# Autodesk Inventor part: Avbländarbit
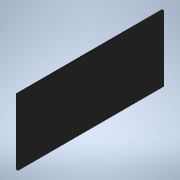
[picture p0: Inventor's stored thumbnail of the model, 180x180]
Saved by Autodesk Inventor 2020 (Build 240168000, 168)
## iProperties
Created: 2019-06
Part Number: Avbländarbit
Material: Acetal Resin, Black
Document SubType Name: Modeling
Designer: cl
Density: 1.425 g/cm^3
Appearance: Smooth - Black
Author: cl
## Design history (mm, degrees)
sketch "Sketch1"
  geometry: L1 (5, 0)-(40, 0); L2 (45, -5)-(45, -95); L3 (40, -100)-(5, -100); L4 (0, -95)-(0, -5); A1 r 5 centre (40, -5) between (45, -5) and (40, 0); A2 r 5 centre (5, -5) between (5, 0) and (0, -5); A3 r 5 centre (5, -95) between (0, -95) and (5, -100); A4 r 5 centre (40, -95) between (40, -100) and (45, -95); 4 further points
  constraints: 8 end point, 8 point on circle, 8 point on line, 8 tangent, 4 centre point, 3 equal radius, 2 parallel, 1 horizontal, 1 perpendicular
  dimensions: "d0" = 45 distance of point (45, -100) point (0, -100); "d1" = 100 distance of point (45, 0) point (45, -100); "d4" = 5 radius of A1
extrude "Extrusion1" new body sketch "Sketch1" distance "d2" = 1.5; taper "d3" = 0 deg
body "Solid1"
